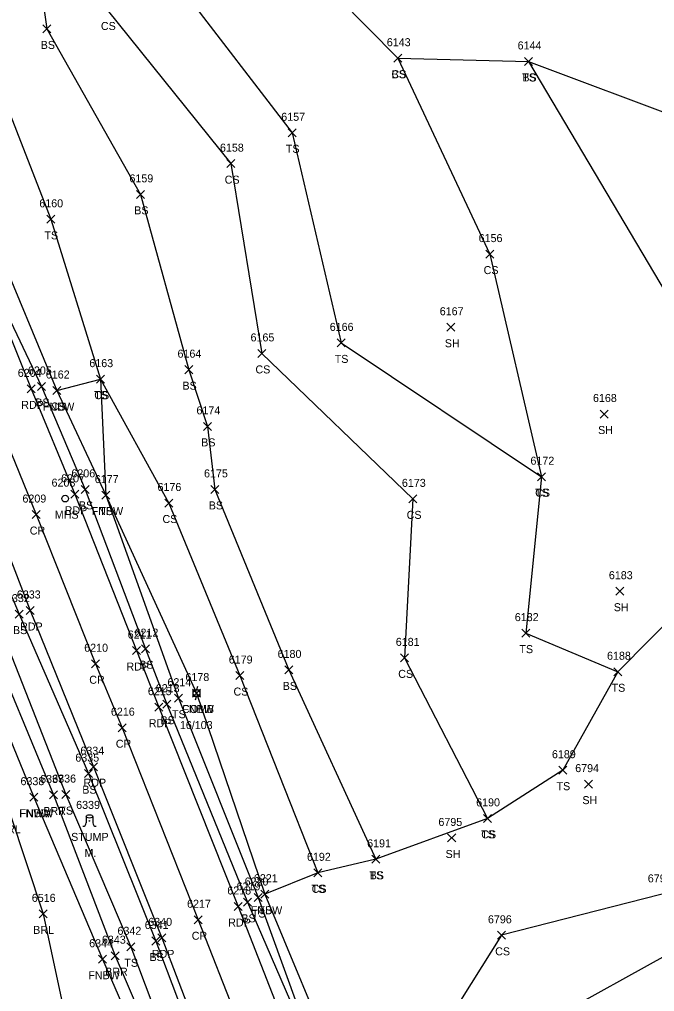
# Model space of a CAD drawing. Extents: x 1472233 to 1475777, y 540726 to 543442.
# Drawn here: x 1472552.6 to 1472711.3, y 541477.9 to 541720.8 of the extents above; entities that cross this region are included whole.
import ezdxf

# ---------------------------------------------------------------- set-up
doc = ezdxf.new("R2010")
doc.units = 0
for name, color, linetype in [('L_A', 7, 'Continuous'), ('L_C', 7, 'Continuous'), ('L_I', 7, 'Continuous'), ('L_TIC', 7, 'Continuous'), ('LABL', 7, 'Continuous'), ('LELB', 7, 'Continuous'), ('LFNC', 7, 'Continuous'), ('LTS', 7, 'Continuous'), ('P_A', 7, 'Continuous'), ('P_I', 7, 'Continuous'), ('P_TIC', 7, 'Continuous'), ('PET', 7, 'Continuous'), ('PRC', 7, 'Continuous'), ('U_A', 7, 'Continuous'), ('U_I', 7, 'Continuous'), ('UP', 7, 'Continuous'), ('USMH', 7, 'Continuous')]:
    doc.layers.add(name, color=color, linetype=linetype)

msp = doc.modelspace()

# ---------------------------------------------------------------- linework, layer by layer
at = {"layer": 'L_TIC'}
for points in [[(1472558.5, 541717.42), (1472560.5, 541719.42)], [(1472560.5, 541717.42), (1472558.5, 541719.42)], [(1472646.14, 541710.1), (1472648.14, 541712.1)], [(1472648.14, 541710.1), (1472646.14, 541712.1)], [(1472646.14, 541710.1), (1472648.14, 541712.1)], [(1472648.14, 541710.1), (1472646.14, 541712.1)], [(1472678.82, 541709.29), (1472680.82, 541711.29)], [(1472680.82, 541709.29), (1472678.82, 541711.29)], [(1472678.82, 541709.29), (1472680.82, 541711.29)], [(1472680.82, 541709.29), (1472678.82, 541711.29)], [(1472619.77, 541691.46), (1472621.77, 541693.46)], [(1472621.77, 541691.46), (1472619.77, 541693.46)], [(1472604.46, 541683.75), (1472606.46, 541685.75)], [(1472606.46, 541683.75), (1472604.46, 541685.75)], [(1472581.86, 541676.08), (1472583.86, 541678.08)], [(1472583.86, 541676.08), (1472581.86, 541678.08)], [(1472559.46, 541669.84), (1472561.46, 541671.84)], [(1472561.46, 541669.84), (1472559.46, 541671.84)], [(1472669.14, 541661.15), (1472671.14, 541663.15)], [(1472671.14, 541661.15), (1472669.14, 541663.15)], [(1472659.4, 541642.87), (1472661.4, 541644.87)], [(1472661.4, 541642.87), (1472659.4, 541644.87)], [(1472631.98, 541638.96), (1472633.98, 541640.96)], [(1472633.98, 541638.96), (1472631.98, 541640.96)], [(1472612.15, 541636.33), (1472614.15, 541638.33)], [(1472614.15, 541636.33), (1472612.15, 541638.33)], [(1472571.87, 541629.9), (1472573.87, 541631.9)], [(1472573.87, 541629.9), (1472571.87, 541631.9)], [(1472571.87, 541629.9), (1472573.87, 541631.9)], [(1472573.87, 541629.9), (1472571.87, 541631.9)], [(1472593.91, 541632.27), (1472595.91, 541634.27)], [(1472595.91, 541632.27), (1472593.91, 541634.27)], [(1472557.15, 541628.07), (1472559.15, 541630.07)], [(1472559.15, 541628.07), (1472557.15, 541630.07)], [(1472561.01, 541627.06), (1472563.01, 541629.06)], [(1472563.01, 541627.06), (1472561.01, 541629.06)], [(1472561.01, 541627.06), (1472563.01, 541629.06)], [(1472563.01, 541627.06), (1472561.01, 541629.06)], [(1472697.69, 541621.19), (1472699.69, 541623.19)], [(1472699.69, 541621.19), (1472697.69, 541623.19)], [(1472598.59, 541618.1), (1472600.59, 541620.1)], [(1472600.59, 541618.1), (1472598.59, 541620.1)], [(1472682.02, 541605.52), (1472684.02, 541607.52)], [(1472684.02, 541605.52), (1472682.02, 541607.52)], [(1472682.02, 541605.52), (1472684.02, 541607.52)], [(1472684.02, 541605.52), (1472682.02, 541607.52)], [(1472568.04, 541602.36), (1472570.04, 541604.36)], [(1472570.04, 541602.36), (1472568.04, 541604.36)], [(1472573.19, 541600.93), (1472575.19, 541602.93)], [(1472575.19, 541600.93), (1472573.19, 541602.93)], [(1472573.19, 541600.93), (1472575.19, 541602.93)], [(1472575.19, 541600.93), (1472573.19, 541602.93)], [(1472600.48, 541602.35), (1472602.48, 541604.35)], [(1472602.48, 541602.35), (1472600.48, 541604.35)], [(1472588.92, 541598.95), (1472590.92, 541600.95)], [(1472590.92, 541598.95), (1472588.92, 541600.95)], [(1472649.91, 541599.98), (1472651.91, 541601.98)], [(1472651.91, 541599.98), (1472649.91, 541601.98)], [(1472701.61, 541576.91), (1472703.61, 541578.91)], [(1472703.61, 541576.91), (1472701.61, 541578.91)], [(1472551.58, 541571.19), (1472553.58, 541573.19)], [(1472553.58, 541571.19), (1472551.58, 541573.19)], [(1472678.11, 541566.43), (1472680.11, 541568.43)], [(1472680.11, 541566.43), (1472678.11, 541568.43)], [(1472583.13, 541562.55), (1472585.13, 541564.55)], [(1472585.13, 541562.55), (1472583.13, 541564.55)], [(1472647.81, 541560.25), (1472649.81, 541562.25)], [(1472649.81, 541560.25), (1472647.81, 541562.25)], [(1472618.95, 541557.24), (1472620.95, 541559.24)], [(1472620.95, 541557.24), (1472618.95, 541559.24)], [(1472606.67, 541555.83), (1472608.67, 541557.83)], [(1472608.67, 541555.83), (1472606.67, 541557.83)], [(1472701.15, 541556.78), (1472703.15, 541558.78)], [(1472703.15, 541556.78), (1472701.15, 541558.78)], [(1472701.15, 541556.78), (1472703.15, 541558.78)], [(1472703.15, 541556.78), (1472701.15, 541558.78)], [(1472591.34, 541550.17), (1472593.34, 541552.17)], [(1472593.34, 541550.17), (1472591.34, 541552.17)], [(1472595.84, 541551.46), (1472597.84, 541553.46)], [(1472597.84, 541551.46), (1472595.84, 541553.46)], [(1472588.42, 541548.68), (1472590.42, 541550.68)], [(1472590.42, 541548.68), (1472588.42, 541550.68)], [(1472568.89, 541531.32), (1472570.89, 541533.32)], [(1472570.89, 541531.32), (1472568.89, 541533.32)], [(1472687.39, 541532.18), (1472689.39, 541534.18)], [(1472689.39, 541532.18), (1472687.39, 541534.18)], [(1472693.77, 541528.7), (1472695.77, 541530.7)], [(1472695.77, 541528.7), (1472693.77, 541530.7)], [(1472555.2, 541525.44), (1472557.2, 541527.44)], [(1472557.2, 541525.44), (1472555.2, 541527.44)], [(1472555.2, 541525.44), (1472557.2, 541527.44)], [(1472557.2, 541525.44), (1472555.2, 541527.44)], [(1472560.11, 541525.99), (1472562.11, 541527.99)], [(1472562.11, 541525.99), (1472560.11, 541527.99)], [(1472563.19, 541526.09), (1472565.19, 541528.09)], [(1472565.19, 541526.09), (1472563.19, 541528.09)], [(1472668.54, 541520.15), (1472670.54, 541522.15)], [(1472670.54, 541520.15), (1472668.54, 541522.15)], [(1472668.54, 541520.15), (1472670.54, 541522.15)], [(1472670.54, 541520.15), (1472668.54, 541522.15)], [(1472659.6, 541515.25), (1472661.6, 541517.25)], [(1472661.6, 541515.25), (1472659.6, 541517.25)], [(1472640.66, 541509.91), (1472642.66, 541511.91)], [(1472642.66, 541509.91), (1472640.66, 541511.91)], [(1472640.66, 541509.91), (1472642.66, 541511.91)], [(1472642.66, 541509.91), (1472640.66, 541511.91)], [(1472626.19, 541506.54), (1472628.19, 541508.54)], [(1472628.19, 541506.54), (1472626.19, 541508.54)], [(1472626.19, 541506.54), (1472628.19, 541508.54)], [(1472628.19, 541506.54), (1472626.19, 541508.54)], [(1472612.94, 541501.19), (1472614.94, 541503.19)], [(1472614.94, 541501.19), (1472612.94, 541503.19)], [(1472612.94, 541501.19), (1472614.94, 541503.19)], [(1472614.94, 541501.19), (1472612.94, 541503.19)], [(1472608.63, 541499.17), (1472610.63, 541501.17)], [(1472610.63, 541499.17), (1472608.63, 541501.17)], [(1472611.27, 541500.36), (1472613.27, 541502.36)], [(1472613.27, 541500.36), (1472611.27, 541502.36)], [(1472557.52, 541496.28), (1472559.52, 541498.28)], [(1472559.52, 541496.28), (1472557.52, 541498.28)], [(1472585.68, 541489.5), (1472587.68, 541491.5)], [(1472587.68, 541489.5), (1472585.68, 541491.5)], [(1472672.02, 541490.92), (1472674.02, 541492.92)], [(1472674.02, 541490.92), (1472672.02, 541492.92)], [(1472579.43, 541488.05), (1472581.43, 541490.05)], [(1472581.43, 541488.05), (1472579.43, 541490.05)], [(1472572.35, 541484.94), (1472574.35, 541486.94)], [(1472574.35, 541484.94), (1472572.35, 541486.94)], [(1472575.55, 541485.83), (1472577.55, 541487.83)], [(1472577.55, 541485.83), (1472575.55, 541487.83)]]:
    msp.add_lwpolyline(points, dxfattribs=at)
at = {"layer": 'LABL'}
for points in [[(1472524.54, 541604.06), (1472530.88, 541605.13), (1472533.72, 541596.51), (1472543.81, 541568.69), (1472561.11, 541526.99), (1472576.55, 541486.83), (1472594.93, 541443.93), (1472607.93, 541409.65), (1472612.47, 541392.9)], [(1472524.54, 541604.06), (1472528.33, 541570.22), (1472538.7, 541544.98), (1472550.2, 541522.43), (1472558.52, 541497.28), (1472565.16, 541466.54), (1472574.97, 541434.22), (1472580.58, 541408.64), (1472585.1, 541401.08), (1472607.18, 541381.96), (1472612.47, 541392.9)]]:
    msp.add_lwpolyline(points, dxfattribs=at)
at = {"layer": 'LELB'}
for points in [[(1472484.34, 541840.42), (1472503.72, 541844.51), (1472532.46, 541842.42), (1472563.08, 541843.09), (1472596.05, 541839.75), (1472588.73, 541808.27), (1472589.55, 541776.06), (1472591.58, 541745.79), (1472593.4, 541728.16), (1472620.77, 541692.46), (1472632.98, 541639.96), (1472683.02, 541606.52), (1472679.11, 541567.43), (1472702.15, 541557.78), (1472688.39, 541533.18), (1472669.54, 541521.15), (1472641.66, 541510.91), (1472627.19, 541507.54), (1472613.94, 541502.19)], [(1472503.72, 541844.51), (1472529.16, 541802.02), (1472541.61, 541765.95), (1472557.39, 541733), (1472559.5, 541718.42), (1472582.86, 541677.08), (1472594.91, 541633.27), (1472599.59, 541619.1), (1472601.48, 541603.35), (1472619.95, 541558.24), (1472641.66, 541510.91)], [(1472563.08, 541843.09), (1472556.25, 541803.25), (1472565.13, 541770.96), (1472571.21, 541739.41), (1472574.54, 541723.15), (1472605.46, 541684.75), (1472613.15, 541637.33), (1472650.91, 541600.98), (1472648.81, 541561.25), (1472669.54, 541521.15)], [(1472484.34, 541840.42), (1472508.51, 541798.7), (1472519.34, 541760.36), (1472543.64, 541727.26), (1472543.24, 541715), (1472560.46, 541670.84), (1472572.87, 541630.9), (1472574.19, 541601.93), (1472592.34, 541551.17), (1472612.27, 541501.36), (1472628.64, 541456.14), (1472641.03, 541420.94), (1472653.51, 541391.46), (1472656.79, 541384.97), (1472662.92, 541362.2), (1472669.18, 541346.61), (1472674.21, 541333.47)], [(1472448.1, 541812.75), (1472448.35, 541808.89), (1472456.83, 541789.05), (1472474.31, 541748.23), (1472493.04, 541702.8), (1472494.57, 541702.64), (1472518, 541641.77), (1472527.77, 541616.94), (1472533.94, 541611.96), (1472541.35, 541598.76), (1472552.58, 541572.19), (1472569.89, 541532.32), (1472586.68, 541490.5), (1472602.95, 541447.47), (1472614.29, 541413.72), (1472616.34, 541394.53)], [(1472617.23, 541741.44), (1472647.14, 541711.1), (1472670.14, 541662.15), (1472683.02, 541606.52)], [(1472647.14, 541711.1), (1472679.82, 541710.29), (1472719.38, 541695.47), (1472750.03, 541634.64), (1472756.43, 541622.87), (1472779.44, 541600.18), (1472777.73, 541574.01), (1472763.61, 541565.88), (1472741.51, 541564.11), (1472730.89, 541554.7), (1472748.86, 541515.07), (1472739.19, 541496.24), (1472714.82, 541487.3), (1472686.31, 541471.49), (1472666.86, 541447.13), (1472662.79, 541441.55), (1472668.41, 541419.29), (1472673.24, 541412.97), (1472671.11, 541405.46), (1472675.13, 541398.08)], [(1472679.82, 541710.29), (1472727.68, 541629.6), (1472734.97, 541618.66), (1472756.59, 541596.09), (1472738.88, 541583.57), (1472718.5, 541574.33), (1472702.15, 541557.78)], [(1472540.25, 541666.6), (1472558.15, 541629.07), (1472569.04, 541603.36), (1472584.13, 541563.55), (1472589.42, 541549.68), (1472609.63, 541500.17), (1472628.64, 541456.14), (1472643.16, 541421.95), (1472658.35, 541390.54), (1472659.79, 541385.27), (1472666.4, 541363.57), (1472670.68, 541348), (1472676.96, 541338.56), (1472681.26, 541333.23)], [(1472562.01, 541628.06), (1472572.87, 541630.9), (1472589.92, 541599.95), (1472607.67, 541556.83), (1472627.19, 541507.54)], [(1472530.88, 541605.13), (1472536.76, 541597.99), (1472547.28, 541570.04), (1472564.19, 541527.09), (1472580.43, 541489.05), (1472596.95, 541445.28), (1472610.61, 541411.36), (1472616.34, 541394.53), (1472627.95, 541364.05), (1472634.3, 541352.48), (1472639.77, 541346.17), (1472644.32, 541334.93), (1472647.68, 541327.12), (1472650.87, 541311.53), (1472653.05, 541303.09), (1472658.89, 541293.28), (1472670.29, 541260.53), (1472686.41, 541223.33)], [(1472748.86, 541515.07), (1472733.37, 541506.2), (1472712.89, 541502.15), (1472673.02, 541491.92), (1472657.9, 541467.84), (1472650.16, 541450.02), (1472653.6, 541432.29), (1472661.59, 541419.53), (1472668.41, 541419.29), (1472679.96, 541433.41), (1472687.47, 541437)]]:
    msp.add_lwpolyline(points, dxfattribs=at)
at = {"layer": 'LFNC'}
for points in [[(1472546.47, 541665.22), (1472562.01, 541628.06), (1472574.19, 541601.93), (1472596.84, 541552.46), (1472613.94, 541502.19), (1472632.53, 541457.54), (1472645.3, 541423.6), (1472667.84, 541394.65), (1472670.15, 541396.24), (1472675.13, 541398.08), (1472685.24, 541400.01)], [(1472529.5, 541596.03), (1472539.01, 541568.49), (1472556.2, 541526.44)], [(1472556.2, 541526.44), (1472573.35, 541485.94), (1472591.86, 541443.5), (1472605.44, 541408.32), (1472612.47, 541392.9), (1472623.1, 541363.11)]]:
    msp.add_lwpolyline(points, dxfattribs=at)
at = {"layer": 'LTS'}
for p, q in [((1472569.28, 541521.65), (1472569.28, 541519.99)), ((1472570.11, 541520.51), (1472570.11, 541520.51)), ((1472570.11, 541520.51), (1472570.11, 541520.51)), ((1472570.11, 541520.49), (1472570.11, 541520.49)), ((1472570.95, 541521.49), (1472570.95, 541521.65)), ((1472570.95, 541521.65), (1472570.95, 541519.99))]:
    msp.add_line(p, q, dxfattribs=at)
msp.add_circle((1472570.11, 541520.51), 0.0833, dxfattribs=at)
for centre, start, end in [((1472568.45, 541519.99), 270, 360), ((1472571.78, 541519.99), 180, 270)]:
    msp.add_arc(centre, 0.833, start, end, dxfattribs=at)
msp.add_ellipse((1472570.11, 541521.65), major_axis=(-0.833, 0), ratio=0.5, dxfattribs=at)
at = {"layer": 'P_TIC'}
for points in [[(1472554.59, 541627.47), (1472556.59, 541629.47)], [(1472556.59, 541627.47), (1472554.59, 541629.47)], [(1472565.44, 541601.13), (1472567.44, 541603.13)], [(1472567.44, 541601.13), (1472565.44, 541603.13)], [(1472555.77, 541596.06), (1472557.77, 541598.06)], [(1472557.77, 541596.06), (1472555.77, 541598.06)], [(1472554.29, 541572.09), (1472556.29, 541574.09)], [(1472556.29, 541572.09), (1472554.29, 541574.09)], [(1472580.86, 541562.08), (1472582.86, 541564.08)], [(1472582.86, 541562.08), (1472580.86, 541564.08)], [(1472570.64, 541558.78), (1472572.64, 541560.78)], [(1472572.64, 541558.78), (1472570.64, 541560.78)], [(1472586.45, 541547.93), (1472588.45, 541549.93)], [(1472588.45, 541547.93), (1472586.45, 541549.93)], [(1472577.28, 541542.8), (1472579.28, 541544.8)], [(1472579.28, 541542.8), (1472577.28, 541544.8)], [(1472570.16, 541533.06), (1472572.16, 541535.06)], [(1472572.16, 541533.06), (1472570.16, 541535.06)], [(1472606.29, 541498.12), (1472608.29, 541500.12)], [(1472608.29, 541498.12), (1472606.29, 541500.12)], [(1472596.24, 541494.81), (1472598.24, 541496.81)], [(1472598.24, 541494.81), (1472596.24, 541496.81)], [(1472587.21, 541490.28), (1472589.21, 541492.28)], [(1472589.21, 541490.28), (1472587.21, 541492.28)]]:
    msp.add_lwpolyline(points, dxfattribs=at)
at = {"layer": 'PET'}
for points in [[(1472431.81, 541951), (1472434.94, 541942.83), (1472440.19, 541926.31), (1472454.88, 541886.72), (1472470.9, 541847.46), (1472487.25, 541799.16), (1472502.86, 541758.42), (1472521.3, 541713.6), (1472521.81, 541711.24), (1472540.25, 541666.6), (1472555.59, 541628.47), (1472566.44, 541602.13), (1472581.86, 541563.08), (1472587.45, 541548.93), (1472607.29, 541499.12), (1472625.04, 541453.69), (1472638.62, 541419.6), (1472649.94, 541390.39), (1472660.9, 541361.79), (1472670.65, 541335.94), (1472680.31, 541310.93), (1472684.25, 541300.56), (1472697.31, 541267.54), (1472711.09, 541230.89)], [(1472410.42, 541944.75), (1472417.04, 541924.07), (1472429.27, 541890.41), (1472437.03, 541868.87), (1472443.66, 541851.19), (1472458.48, 541813.05), (1472466.78, 541792.24), (1472482.95, 541751.29), (1472501.43, 541706.5), (1472501.82, 541705.19), (1472522.02, 541654.99), (1472538.62, 541615.01), (1472544.85, 541600.28), (1472555.29, 541573.09), (1472571.16, 541534.06), (1472588.21, 541491.28), (1472604.53, 541448.36), (1472617.02, 541415.32), (1472632.48, 541374.1), (1472640.33, 541354.3), (1472653.53, 541321.3), (1472663.39, 541294.75), (1472676.2, 541262.98), (1472690.88, 541224.88)]]:
    msp.add_lwpolyline(points, dxfattribs=at)
at = {"layer": 'PRC'}
msp.add_lwpolyline([(1472420.86, 541948.25), (1472433.46, 541909.93), (1472447.3, 541871.91), (1472463.52, 541829.07), (1472476.48, 541795.89), (1472493.07, 541754.32), (1472510.83, 541710.45), (1472511.85, 541707.67), (1472530.21, 541662.33), (1472546.22, 541622.93), (1472556.77, 541597.06), (1472571.64, 541559.78), (1472578.28, 541543.8), (1472597.24, 541495.81), (1472616.73, 541446.14), (1472628.52, 541416.05), (1472640.35, 541384.78), (1472651, 541357.43), (1472663.57, 541324.45), (1472674.03, 541297.85), (1472686.99, 541264.4), (1472700.97, 541228.15)], dxfattribs=at)
at = {"layer": 'UP'}
for p, q in [((1472596, 541551.63), (1472596, 541553.3)), ((1472596, 541553.3), (1472597.67, 541553.3)), ((1472597.09, 541554.13), (1472596.84, 541553.3)), ((1472596.84, 541552.46), (1472596.84, 541552.46)), ((1472597.67, 541553.3), (1472597.67, 541551.63)), ((1472597.67, 541551.63), (1472596, 541551.63)), ((1472596.59, 541550.8), (1472596.84, 541551.63))]:
    msp.add_line(p, q, dxfattribs=at)
msp.add_circle((1472596.84, 541552.46), 0.833, dxfattribs=at)
at = {"layer": 'USMH'}
for p, q in [((1472564.04, 541601.04), (1472564.04, 541601.04)), ((1472564.87, 541601.04), (1472564.87, 541601.04))]:
    msp.add_line(p, q, dxfattribs=at)
msp.add_circle((1472564.04, 541601.04), 0.833, dxfattribs=at)

# ---------------------------------------------------------------- texts
at = {"layer": 'L_A'}
for s, p in [('CS', (1472572.98, 541718.15)), ('BS', (1472557.94, 541713.42)), ('CS', (1472645.58, 541706.1)), ('BS', (1472645.58, 541706.1)), ('TS', (1472678.23, 541705.29)), ('BS', (1472678.26, 541705.29)), ('TS', (1472619.18, 541687.46)), ('CS', (1472603.9, 541679.75)), ('BS', (1472581.3, 541672.08)), ('TS', (1472558.87, 541665.84)), ('CS', (1472668.58, 541657.15)), ('SH', (1472658.89, 541638.87)), ('TS', (1472631.39, 541634.96)), ('CS', (1472611.59, 541632.33)), ('BS', (1472593.35, 541628.27)), ('TS', (1472571.28, 541625.9)), ('CS', (1472571.32, 541625.9)), ('BS', (1472556.59, 541624.07)), ('FNBW', (1472558.48, 541623.06)), ('CS', (1472560.45, 541623.06)), ('SH', (1472697.18, 541617.19)), ('BS', (1472598.03, 541614.1)), ('TS', (1472681.43, 541601.52)), ('CS', (1472681.46, 541601.52)), ('BS', (1472567.48, 541598.36)), ('BS', (1472599.92, 541598.35)), ('FNBW', (1472570.67, 541596.93)), ('TS', (1472572.6, 541596.93)), ('CS', (1472649.35, 541595.98)), ('CS', (1472588.36, 541594.95)), ('SH', (1472701.1, 541572.91)), ('BS', (1472551.02, 541567.19)), ('TS', (1472677.52, 541562.43)), ('BS', (1472582.57, 541558.55)), ('CS', (1472647.25, 541556.25)), ('BS', (1472618.39, 541553.24)), ('TS', (1472700.56, 541552.78)), ('TS', (1472700.56, 541552.78)), ('CS', (1472606.11, 541551.83)), ('FNBW', (1472593.31, 541547.46)), ('TS', (1472590.75, 541546.17)), ('BS', (1472587.86, 541544.68)), ('TS', (1472686.8, 541528.18)), ('BS', (1472568.33, 541527.32)), ('SH', (1472693.26, 541524.7)), ('FNWW', (1472552.54, 541521.44)), ('FNBW', (1472552.67, 541521.44)), ('BRR', (1472558.6, 541521.99)), ('TS', (1472562.6, 541522.09)), ('BRL', (1472547.74, 541517.43)), ('TS', (1472667.95, 541516.15)), ('CS', (1472667.99, 541516.15)), ('STUMP', (1472565.54, 541515.51)), ('SH', (1472659.08, 541511.25)), ('TS', (1472640.07, 541505.91)), ('BS', (1472640.11, 541505.91)), ('TS', (1472625.6, 541502.54)), ('CS', (1472625.63, 541502.54)), ('FNBW', (1472610.41, 541497.19)), ('TS', (1472610.68, 541496.36)), ('TS', (1472612.35, 541497.19)), ('BS', (1472608.07, 541495.17)), ('BRL', (1472556.06, 541492.28)), ('CS', (1472671.47, 541486.92)), ('BS', (1472585.12, 541485.5)), ('BRR', (1472574.04, 541481.83)), ('TS', (1472578.84, 541484.05)), ('FNBW', (1472569.83, 541480.94))]:
    msp.add_text(s, height=2, dxfattribs=at).set_placement(p)
at = {"layer": 'L_C'}
for s, p in [('16/103', (1472592.71, 541543.46)), ('M.', (1472568.88, 541511.51))]:
    msp.add_text(s, height=2, dxfattribs=at).set_placement(p)
at = {"layer": 'L_I'}
for s, p in [('6143', (1472644.4, 541714.1)), ('6143', (1472644.4, 541714.1)), ('6144', (1472677.08, 541713.29)), ('6144', (1472677.08, 541713.29)), ('6157', (1472618.03, 541695.46)), ('6158', (1472602.72, 541687.75)), ('6159', (1472580.11, 541680.08)), ('6160', (1472557.59, 541673.84)), ('6156', (1472667.34, 541665.15)), ('6167', (1472657.62, 541646.87)), ('6166', (1472630.14, 541642.96)), ('6165', (1472610.36, 541640.33)), ('6164', (1472592.12, 541636.27)), ('6163', (1472570.09, 541633.9)), ('6163', (1472570.09, 541633.9)), ('6205', (1472554.76, 541632.07)), ('6162', (1472559.22, 541631.06)), ('6162', (1472559.22, 541631.06)), ('6168', (1472695.9, 541625.19)), ('6174', (1472596.85, 541622.1)), ('6172', (1472680.28, 541609.52)), ('6172', (1472680.28, 541609.52)), ('6206', (1472565.6, 541606.36)), ('6175', (1472598.74, 541606.35)), ('6177', (1472571.45, 541604.93)), ('6177', (1472571.45, 541604.93)), ('6173', (1472648.17, 541603.98)), ('6176', (1472587.12, 541602.95)), ('6183', (1472699.87, 541580.91)), ('6332', (1472549.27, 541575.19)), ('6182', (1472676.37, 541570.43)), ('6212', (1472581.39, 541566.55)), ('6181', (1472646.64, 541564.25)), ('6179', (1472604.92, 541559.83)), ('6180', (1472617.12, 541561.24)), ('6188', (1472699.41, 541560.78)), ('6188', (1472699.41, 541560.78)), ('6178', (1472594.1, 541555.46)), ('6213', (1472586.68, 541552.68)), ('6214', (1472589.6, 541554.17)), ('6335', (1472566.59, 541535.32)), ('6189', (1472685.65, 541536.18)), ('6794', (1472691.46, 541532.7)), ('6338', (1472552.89, 541529.44)), ('6338', (1472552.89, 541529.44)), ('6337', (1472557.8, 541529.99)), ('6336', (1472560.82, 541530.09)), ('6339', (1472566.8, 541523.51)), ('6190', (1472666.72, 541524.15)), ('6190', (1472666.72, 541524.15)), ('6795', (1472657.29, 541519.25)), ('6191', (1472639.49, 541513.91)), ('6191', (1472639.49, 541513.91)), ('6192', (1472624.45, 541510.54)), ('6192', (1472624.45, 541510.54)), ('6220', (1472608.88, 541504.36)), ('6221', (1472611.2, 541505.19)), ('6221', (1472611.2, 541505.19)), ('6793', (1472709.59, 541505.15)), ('6219', (1472606.88, 541503.17)), ('6516', (1472555.72, 541500.28)), ('6796', (1472669.66, 541494.92)), ('6342', (1472577.12, 541492.05)), ('6341', (1472583.94, 541493.5)), ('6343', (1472573.24, 541489.83)), ('6344', (1472570.05, 541488.94))]:
    msp.add_text(s, height=2, dxfattribs=at).set_placement(p)
at = {"layer": 'P_A'}
for s, p in [('RDP', (1472553.08, 541623.47)), ('RDP', (1472563.92, 541597.13)), ('CR', (1472555.21, 541592.06)), ('RDP', (1472552.78, 541568.09)), ('RDP', (1472579.35, 541558.08)), ('CR', (1472570.07, 541554.78)), ('RDP', (1472584.94, 541543.93)), ('CR', (1472576.71, 541538.8)), ('RDP', (1472568.64, 541529.06)), ('RDP', (1472604.78, 541494.12)), ('CR', (1472595.67, 541490.81)), ('RDP', (1472585.7, 541486.28))]:
    msp.add_text(s, height=2, dxfattribs=at).set_placement(p)
at = {"layer": 'P_I'}
for s, p in [('6204', (1472552.21, 541631.47)), ('6207', (1472563.05, 541605.13)), ('6209', (1472553.38, 541600.06)), ('6333', (1472551.98, 541576.09)), ('6211', (1472579.68, 541566.08)), ('6210', (1472568.81, 541562.78)), ('6215', (1472584.71, 541551.93)), ('6216', (1472575.48, 541546.8)), ('6334', (1472567.85, 541537.06)), ('6218', (1472604.55, 541502.12)), ('6217', (1472594.5, 541498.81)), ('6340', (1472584.81, 541494.28))]:
    msp.add_text(s, height=2, dxfattribs=at).set_placement(p)
at = {"layer": 'U_A'}
for s, p in [('MHS', (1472561.45, 541596.04)), ('COMB', (1472593.22, 541547.46))]:
    msp.add_text(s, height=2, dxfattribs=at).set_placement(p)
at = {"layer": 'U_I'}
for s, p in [('6208', (1472560.65, 541604.04)), ('6178', (1472594.1, 541555.46))]:
    msp.add_text(s, height=2, dxfattribs=at).set_placement(p)

doc.saveas('drawing.dxf')
